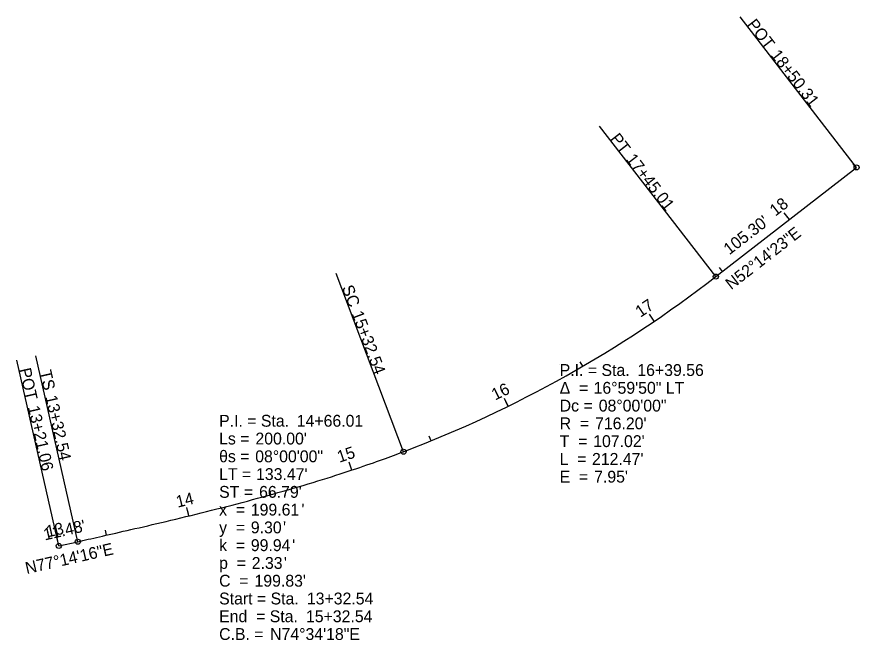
# Model space of a CAD drawing. Extents: x 2196298 to 2196796, y 661650 to 662018.
import ezdxf

# ---------------------------------------------------------------- set-up
doc = ezdxf.new("R2010")
doc.units = 0
for name, color, linetype in [('Default', 7, 'Continuous'), ('GE_X_Alignment', 7, 'Continuous'), ('GE_X_Alignment_1000_Curve_Data', 7, 'Continuous'), ('GE_X_Alignment_1000_Stations', 7, 'Continuous'), ('GE_X_Alignment_100_Curve_Data', 7, 'Continuous'), ('GE_X_Alignment_100_Stations', 7, 'Continuous'), ('GE_X_Alignment_500_Curve_Data', 7, 'Continuous'), ('GE_X_Alignment_500_Stations', 7, 'Continuous')]:
    doc.layers.add(name, color=color, linetype=linetype)

msp = doc.modelspace()

# ---------------------------------------------------------------- linework, layer by layer
at = {"layer": 'Default'}
for centre in [(2196794.52, 661929.31), (2196794.52, 661929.31), (2196794.52, 661929.31), (2196752.9, 661897.07), (2196752.9, 661897.07), (2196752.9, 661897.07), (2196752.9, 661897.07), (2196752.9, 661897.07), (2196752.9, 661897.07), (2196754.75, 661898.5), (2196711.27, 661864.83), (2196711.27, 661864.83), (2196711.27, 661864.83), (2196674.85, 661838.4), (2196618.93, 661813.09), (2196618.93, 661813.09), (2196618.93, 661813.09), (2196588.45, 661788.2), (2196526.59, 661761.36), (2196526.59, 661761.36), (2196526.59, 661761.36), (2196495.93, 661750.48), (2196495.93, 661750.48), (2196430.28, 661734.77), (2196430.28, 661734.77), (2196430.28, 661734.77), (2196399.68, 661723.44), (2196322.77, 661705.66), (2196322.77, 661705.66), (2196322.77, 661705.66), (2196322.77, 661705.66), (2196328.37, 661706.93), (2196328.37, 661706.93), (2196328.37, 661706.93), (2196328.37, 661706.93), (2196328.37, 661706.93), (2196328.37, 661706.93), (2196333.97, 661708.19), (2196333.97, 661708.19), (2196333.97, 661708.19)]:
    msp.add_circle(centre, 0.0000833, dxfattribs=at)
at = {"layer": 'GE_X_Alignment'}
for p, q in [((2196711.27, 661864.83), (2196794.52, 661929.31)), ((2196322.77, 661705.66), (2196333.97, 661708.19))]:
    msp.add_line(p, q, dxfattribs=at)
msp.add_arc((2196272.7, 662431.04), 716.2, 290.76249, 307.75985, dxfattribs=at)
msp.add_open_spline([(2196333.97, 661708.19), (2196338.03, 661709.12), (2196346.16, 661710.96), (2196362.41, 661714.66), (2196382.71, 661719.35), (2196407.02, 661725.19), (2196431.25, 661731.35), (2196455.37, 661737.93), (2196479.34, 661745.03), (2196499.15, 661751.48), (2196514.88, 661756.99), (2196522.7, 661759.88), (2196526.59, 661761.36)], degree=3, dxfattribs=at)
at = {"layer": 'GE_X_Alignment_1000_Stations'}
for p, q in [((2196794.52, 661929.31), (2196725.63, 662018.25)), ((2196711.27, 661864.83), (2196642.38, 661953.77)), ((2196526.59, 661761.36), (2196486.71, 661866.55)), ((2196322.77, 661705.66), (2196297.92, 661815.38)), ((2196333.97, 661708.19), (2196309.12, 661817.92)), ((2196495.93, 661750.48), (2196494.98, 661753.32)), ((2196322.77, 661705.66), (2196321.67, 661710.54))]:
    msp.add_line(p, q, dxfattribs=at)
for centre in [(2196794.52, 661929.31), (2196711.27, 661864.83), (2196526.59, 661761.36), (2196322.77, 661705.66), (2196333.97, 661708.19)]:
    msp.add_circle(centre, 1.5, dxfattribs=at)
at = {"layer": 'GE_X_Alignment_100_Stations'}
for p, q in [((2196794.52, 661929.31), (2196725.63, 662018.25)), ((2196711.27, 661864.83), (2196642.38, 661953.77)), ((2196794.28, 661929.12), (2196792.44, 661931.49)), ((2196754.75, 661898.5), (2196751.69, 661902.45)), ((2196715.22, 661867.88), (2196713.38, 661870.26)), ((2196526.59, 661761.36), (2196486.71, 661866.55)), ((2196674.85, 661838.4), (2196672.04, 661842.54)), ((2196322.77, 661705.66), (2196297.92, 661815.38)), ((2196333.97, 661708.19), (2196309.12, 661817.92)), ((2196632.53, 661811.79), (2196631.02, 661814.39)), ((2196588.45, 661788.2), (2196586.25, 661792.69)), ((2196542.84, 661767.74), (2196541.71, 661770.52)), ((2196495.93, 661750.48), (2196494.35, 661755.22)), ((2196448.08, 661735.97), (2196447.28, 661738.87)), ((2196399.68, 661723.44), (2196398.5, 661728.3)), ((2196351, 661712.06), (2196350.33, 661714.98))]:
    msp.add_line(p, q, dxfattribs=at)
for centre in [(2196794.52, 661929.31), (2196711.27, 661864.83), (2196526.59, 661761.36), (2196322.77, 661705.66), (2196333.97, 661708.19)]:
    msp.add_circle(centre, 1.5, dxfattribs=at)
at = {"layer": 'GE_X_Alignment_500_Stations'}
for p, q in [((2196794.52, 661929.31), (2196725.63, 662018.25)), ((2196711.27, 661864.83), (2196642.38, 661953.77)), ((2196754.75, 661898.5), (2196752.91, 661900.87)), ((2196526.59, 661761.36), (2196486.71, 661866.55)), ((2196674.85, 661838.4), (2196673.16, 661840.88)), ((2196322.77, 661705.66), (2196297.92, 661815.38)), ((2196333.97, 661708.19), (2196309.12, 661817.92)), ((2196588.45, 661788.2), (2196587.13, 661790.9)), ((2196495.93, 661750.48), (2196494.35, 661755.22)), ((2196399.68, 661723.44), (2196398.97, 661726.36))]:
    msp.add_line(p, q, dxfattribs=at)
for centre in [(2196794.52, 661929.31), (2196711.27, 661864.83), (2196526.59, 661761.36), (2196322.77, 661705.66), (2196333.97, 661708.19)]:
    msp.add_circle(centre, 1.5, dxfattribs=at)

# ---------------------------------------------------------------- texts
at = {"layer": 'GE_X_Alignment_1000_Curve_Data'}
for s, p in [('P.I. = Sta. ', (2196618.93, 661806.09)), ('16+39.56', (2196664.85, 661806.09)), ('Δ  = ', (2196618.93, 661795.59)), ('16°59\'50" LT', (2196638.99, 661795.59)), ('Dc = ', (2196618.93, 661785.09)), ('08°00\'00"', (2196642.03, 661785.09)), ('P.I. = Sta. ', (2196417.54, 661776.12)), ('14+66.01', (2196463.46, 661776.12)), ('R  = ', (2196618.93, 661774.59)), ("716.20'", (2196639.85, 661774.59)), ('Ls = ', (2196417.54, 661765.62)), ("200.00'", (2196439.01, 661765.62)), ('T  = ', (2196618.93, 661764.09)), ("107.02'", (2196638.76, 661764.09)), ('θs = ', (2196417.54, 661755.12)), ('08°00\'00"', (2196438.88, 661755.12)), ('L  = ', (2196618.93, 661753.59)), ("212.47'", (2196638.05, 661753.59)), ('LT = ', (2196417.54, 661744.62)), ("133.47'", (2196439.37, 661744.62)), ('E  = ', (2196618.93, 661743.09)), ("7.95'", (2196639.31, 661743.09)), ('ST = ', (2196417.54, 661734.12)), ("66.79'", (2196441.18, 661734.12)), ('199.61', (2196436.29, 661723.62)), ("'", (2196466.19, 661723.62)), ('x  = ', (2196417.54, 661723.62)), ('9.30', (2196436.29, 661713.12)), ("'", (2196455.32, 661713.12)), ('y  = ', (2196417.54, 661713.12)), ('k  = ', (2196417.54, 661702.62)), ('99.94', (2196436.29, 661702.62)), ("'", (2196460.75, 661702.62)), ('p  = ', (2196417.54, 661692.12)), ('2.33', (2196436.83, 661692.12)), ("'", (2196455.86, 661692.12)), ('C  = ', (2196417.54, 661681.62)), ("199.83'", (2196438.46, 661681.62)), ('Start = Sta. ', (2196417.54, 661671.12)), ('13+32.54', (2196469.44, 661671.12)), ('End  = Sta. ', (2196417.54, 661660.62)), ('15+32.54', (2196468.9, 661660.62)), ('C.B. = ', (2196417.54, 661650.12)), ('N74°34\'18"E', (2196447.7, 661650.12))]:
    msp.add_text(s, height=7, dxfattribs=at).set_placement(p)
at = {"layer": 'GE_X_Alignment_1000_Stations'}
for s, rotation, p in [('POT', 307.7602, (2196729.36, 662013.63)), ('18+50.31', 307.7602, (2196743.34, 661995.58)), ('PT', 307.7602, (2196648.44, 661946.13)), ('17+45.01', 307.7602, (2196657.76, 661934.1)), ("105.30'", 37.7602, (2196719.23, 661877.31)), ('N52°14\'23"E', 37.7602, (2196720.36, 661856.69)), ('SC', 290.7625, (2196489.97, 661858.28)), ('15+32.54', 290.7625, (2196495.75, 661843.04)), ('POT', 282.7621, (2196299.25, 661810.03)), ('TS', 282.7621, (2196311.31, 661808.75)), ('13+32.54', 282.7621, (2196314.68, 661793.91)), ('13+21.06', 282.7621, (2196304.29, 661787.77)), ("11.48'", 12.7621, (2196314.46, 661708.9)), ('13', 12.7621, (2196316.06, 661710.67)), ('N77°14\'16"E', 12.7621, (2196303.76, 661689.05))]:
    msp.add_text(s, height=7, rotation=rotation, dxfattribs=at).set_placement(p)
at = {"layer": 'GE_X_Alignment_100_Curve_Data'}
for s, p in [('P.I. = Sta. ', (2196618.93, 661806.09)), ('16+39.56', (2196664.85, 661806.09)), ('Δ  = ', (2196618.93, 661795.59)), ('16°59\'50" LT', (2196638.99, 661795.59)), ('Dc = ', (2196618.93, 661785.09)), ('08°00\'00"', (2196642.03, 661785.09)), ('P.I. = Sta. ', (2196417.54, 661776.12)), ('14+66.01', (2196463.46, 661776.12)), ('R  = ', (2196618.93, 661774.59)), ("716.20'", (2196639.85, 661774.59)), ('Ls = ', (2196417.54, 661765.62)), ("200.00'", (2196439.01, 661765.62)), ('T  = ', (2196618.93, 661764.09)), ("107.02'", (2196638.76, 661764.09)), ('θs = ', (2196417.54, 661755.12)), ('08°00\'00"', (2196438.88, 661755.12)), ('L  = ', (2196618.93, 661753.59)), ("212.47'", (2196638.05, 661753.59)), ('LT = ', (2196417.54, 661744.62)), ("133.47'", (2196439.37, 661744.62)), ('E  = ', (2196618.93, 661743.09)), ("7.95'", (2196639.31, 661743.09)), ('ST = ', (2196417.54, 661734.12)), ("66.79'", (2196441.18, 661734.12)), ('199.61', (2196436.29, 661723.62)), ("'", (2196466.19, 661723.62)), ('x  = ', (2196417.54, 661723.62)), ('9.30', (2196436.29, 661713.12)), ("'", (2196455.32, 661713.12)), ('y  = ', (2196417.54, 661713.12)), ('k  = ', (2196417.54, 661702.62)), ('99.94', (2196436.29, 661702.62)), ("'", (2196460.75, 661702.62)), ('p  = ', (2196417.54, 661692.12)), ('2.33', (2196436.83, 661692.12)), ("'", (2196455.86, 661692.12)), ('C  = ', (2196417.54, 661681.62)), ("199.83'", (2196438.46, 661681.62)), ('Start = Sta. ', (2196417.54, 661671.12)), ('13+32.54', (2196469.44, 661671.12)), ('End  = Sta. ', (2196417.54, 661660.62)), ('15+32.54', (2196468.9, 661660.62)), ('C.B. = ', (2196417.54, 661650.12)), ('N74°34\'18"E', (2196447.7, 661650.12))]:
    msp.add_text(s, height=7, dxfattribs=at).set_placement(p)
at = {"layer": 'GE_X_Alignment_100_Stations'}
for s, rotation, p in [('POT', 307.7602, (2196729.36, 662013.63)), ('18+50.31', 307.7602, (2196743.34, 661995.58)), ('PT', 307.7602, (2196648.44, 661946.13)), ('17+45.01', 307.7602, (2196657.76, 661934.1)), ('18', 37.7602, (2196746.52, 661900.18)), ("105.30'", 37.7602, (2196719.23, 661877.31)), ('N52°14\'23"E', 37.7602, (2196720.36, 661856.69)), ('SC', 290.7625, (2196489.97, 661858.28)), ('17', 34.1592, (2196666.68, 661840.41)), ('15+32.54', 290.7625, (2196495.75, 661843.04)), ('POT', 282.7621, (2196299.25, 661810.03)), ('TS', 282.7621, (2196311.31, 661808.75)), ('16', 26.1593, (2196580.72, 661791.5)), ('13+32.54', 282.7621, (2196314.68, 661793.91)), ('13+21.06', 282.7621, (2196304.29, 661787.77)), ('15', 18.3707, (2196488.69, 661754.78)), ('14', 13.6723, (2196392.98, 661728.25)), ("11.48'", 12.7621, (2196314.46, 661708.9)), ('N77°14\'16"E', 12.7621, (2196303.76, 661689.05))]:
    msp.add_text(s, height=7, rotation=rotation, dxfattribs=at).set_placement(p)
at = {"layer": 'GE_X_Alignment_500_Curve_Data'}
for s, p in [('P.I. = Sta. ', (2196618.93, 661806.09)), ('16+39.56', (2196664.85, 661806.09)), ('Δ  = ', (2196618.93, 661795.59)), ('16°59\'50" LT', (2196638.99, 661795.59)), ('Dc = ', (2196618.93, 661785.09)), ('08°00\'00"', (2196642.03, 661785.09)), ('P.I. = Sta. ', (2196417.54, 661776.12)), ('14+66.01', (2196463.46, 661776.12)), ('R  = ', (2196618.93, 661774.59)), ("716.20'", (2196639.85, 661774.59)), ('Ls = ', (2196417.54, 661765.62)), ("200.00'", (2196439.01, 661765.62)), ('T  = ', (2196618.93, 661764.09)), ("107.02'", (2196638.76, 661764.09)), ('θs = ', (2196417.54, 661755.12)), ('08°00\'00"', (2196438.88, 661755.12)), ('L  = ', (2196618.93, 661753.59)), ("212.47'", (2196638.05, 661753.59)), ('LT = ', (2196417.54, 661744.62)), ("133.47'", (2196439.37, 661744.62)), ('E  = ', (2196618.93, 661743.09)), ("7.95'", (2196639.31, 661743.09)), ('ST = ', (2196417.54, 661734.12)), ("66.79'", (2196441.18, 661734.12)), ('199.61', (2196436.29, 661723.62)), ("'", (2196466.19, 661723.62)), ('x  = ', (2196417.54, 661723.62)), ('9.30', (2196436.29, 661713.12)), ("'", (2196455.32, 661713.12)), ('y  = ', (2196417.54, 661713.12)), ('k  = ', (2196417.54, 661702.62)), ('99.94', (2196436.29, 661702.62)), ("'", (2196460.75, 661702.62)), ('p  = ', (2196417.54, 661692.12)), ('2.33', (2196436.83, 661692.12)), ("'", (2196455.86, 661692.12)), ('C  = ', (2196417.54, 661681.62)), ("199.83'", (2196438.46, 661681.62)), ('Start = Sta. ', (2196417.54, 661671.12)), ('13+32.54', (2196469.44, 661671.12)), ('End  = Sta. ', (2196417.54, 661660.62)), ('15+32.54', (2196468.9, 661660.62)), ('C.B. = ', (2196417.54, 661650.12)), ('N74°34\'18"E', (2196447.7, 661650.12))]:
    msp.add_text(s, height=7, dxfattribs=at).set_placement(p)
at = {"layer": 'GE_X_Alignment_500_Stations'}
for s, rotation, p in [('POT', 307.7602, (2196729.36, 662013.63)), ('18+50.31', 307.7602, (2196743.34, 661995.58)), ('PT', 307.7602, (2196648.44, 661946.13)), ('17+45.01', 307.7602, (2196657.76, 661934.1)), ("105.30'", 37.7602, (2196719.23, 661877.31)), ('N52°14\'23"E', 37.7602, (2196720.36, 661856.69)), ('SC', 290.7625, (2196489.97, 661858.28)), ('15+32.54', 290.7625, (2196495.75, 661843.04)), ('POT', 282.7621, (2196299.25, 661810.03)), ('TS', 282.7621, (2196311.31, 661808.75)), ('13+32.54', 282.7621, (2196314.68, 661793.91)), ('13+21.06', 282.7621, (2196304.29, 661787.77)), ('15', 18.3707, (2196488.69, 661754.78)), ("11.48'", 12.7621, (2196314.46, 661708.9)), ('N77°14\'16"E', 12.7621, (2196303.76, 661689.05))]:
    msp.add_text(s, height=7, rotation=rotation, dxfattribs=at).set_placement(p)

doc.saveas('drawing.dxf')
